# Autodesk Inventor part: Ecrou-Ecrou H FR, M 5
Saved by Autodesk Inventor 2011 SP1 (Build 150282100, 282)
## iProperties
Created: 2010-12
Part Number: Ecrou-Ecrou H FR, M 5
Document SubType Name: Modeling
Designer: eric
Density: 1 g/cm^3
Mass: 0.201477 g
Surface Area: 3.17131 cm^2
Volume: 0.201477 cm^3
Author: eric
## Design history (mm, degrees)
feature "Base1"
node "Solide1"
node "Corps solides"
node "Corps surfaciques"
